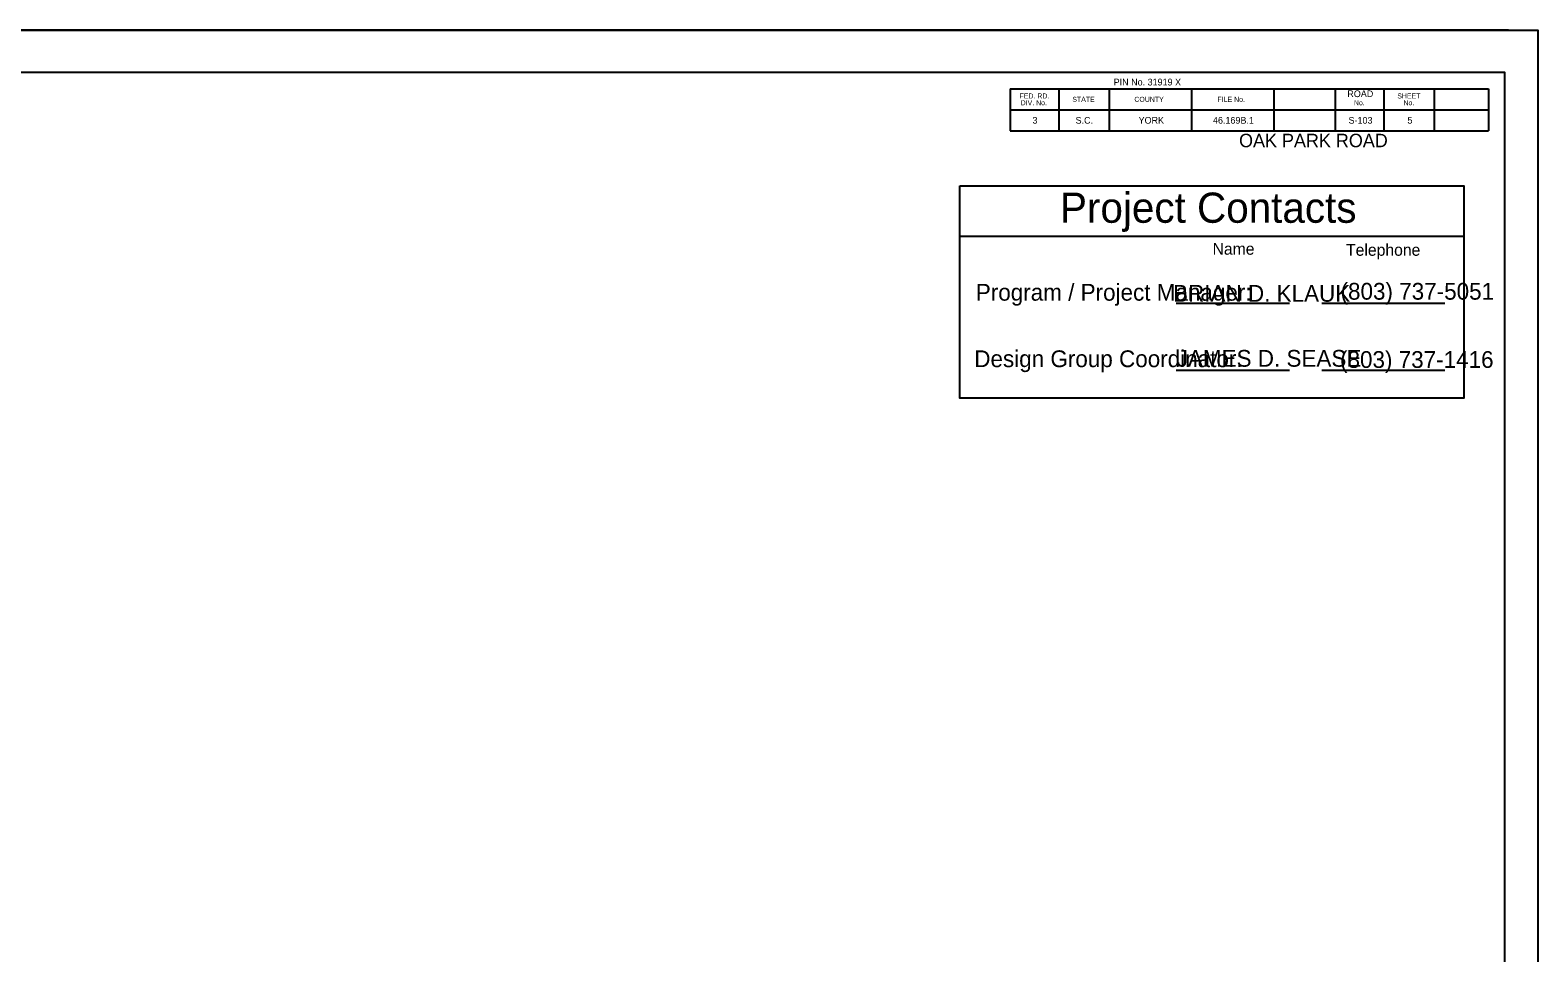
# Model space of a CAD drawing. Extents: x -796 to 2793, y -4650 to 4425.
# Drawn here: x 1879 to 2777, y -2950 to -2400 of the extents above; entities that cross this region are included whole.
import ezdxf

# ---------------------------------------------------------------- set-up
doc = ezdxf.new("R2010")
doc.units = 0
for name, color, linetype in [('RD_HC_CL', 7, 'Continuous'), ('RD_HC_Data', 7, 'Continuous'), ('RD_HC_Data_Tic', 7, 'Continuous'), ('RD_SHT_Bndy', 7, 'Continuous'), ('RD_TX_Misc1', 7, 'Continuous')]:
    doc.layers.add(name, color=color, linetype=linetype)

msp = doc.modelspace()

# ---------------------------------------------------------------- linework, layer by layer
at = {"layer": 'RD_HC_CL'}
msp.add_lwpolyline([(981.4, -2400), (2777.4, -2400), (2777.4, -3500), (981.4, -3500)], close=True, dxfattribs=at)
at = {"layer": 'RD_HC_Data'}
for p, q in [((2760, -2400), (1000, -2400)), ((1000, -2400), (2760, -2400)), ((2463.1, -2435), (2463.1, -2460)), ((2463.1, -2435), (2748.1, -2435)), ((2492.1, -2435), (2492.1, -2460)), ((2522.1, -2435), (2522.1, -2460)), ((2571.1, -2435), (2571.1, -2460)), ((2620.1, -2435), (2620.1, -2460)), ((2656.6, -2435), (2656.6, -2460)), ((2685.6, -2435), (2685.6, -2460)), ((2715.6, -2435), (2715.6, -2460)), ((2748.1, -2435), (2748.1, -2460)), ((2463.1, -2447.5), (2748.1, -2447.5)), ((2463.1, -2460), (2748.1, -2460))]:
    msp.add_line(p, q, dxfattribs=at)
msp.add_lwpolyline([(1082.6, -2425), (2757.6, -2425), (2757.6, -3475), (1082.6, -3475)], close=True, dxfattribs=at)
at = {"layer": 'RD_TX_Misc1'}
for p, q in [((2433.16, -2522.72), (2733.34, -2522.72)), ((2562.03, -2562.72), (2629.41, -2562.72)), ((2648.83, -2562.72), (2721.92, -2562.72)), ((2562.03, -2602.72), (2629.41, -2602.72)), ((2648.83, -2602.72), (2721.92, -2602.72))]:
    msp.add_line(p, q, dxfattribs=at)
msp.add_lwpolyline([(2433.16, -2492.72), (2733.34, -2492.72), (2733.34, -2619.29), (2433.16, -2619.29)], close=True, dxfattribs=at)

# ---------------------------------------------------------------- texts
at = {"layer": 'RD_HC_Data_Tic'}
for s, height, p in [('PIN No. 31919 X   ', 4, (2524.75, -2432.98)), ('FED. RD.', 3, (2468.72, -2440.73)), ('DIV. No.', 3, (2469.34, -2444.77)), ('STATE', 3, (2500.12, -2442.75)), ('COUNTY', 3, (2537.09, -2442.75)), ('FILE No.', 3, (2586.6, -2442.75)), ('      ROAD      ', 4, (2655.02, -2439.93)), ('No.', 3, (2667.86, -2444.77)), ('SHEET', 3, (2693.68, -2440.73)), ('No.', 3, (2697.36, -2444.77)), ('3', 4, (2476.4, -2455.75)), ('S.C.', 4, (2502.08, -2455.75)), ('      YORK      ', 4, (2530.68, -2455.75)), ('   46.169B.1    ', 4, (2579.44, -2455.75)), ('     S-103      ', 4, (2657.22, -2455.75)), ('       5        ', 4, (2689.34, -2455.75)), ('OAK PARK ROAD                 ', 8, (2599.44, -2469.78))]:
    msp.add_text(s, height=height, dxfattribs=at).set_placement(p)
at = {"layer": 'RD_SHT_Bndy'}
for s, p in [('(803) 737-5051', (2659.89, -2560.66)), ('BRIAN D. KLAUK', (2560.14, -2561.89)), ('JAMES D. SEASE', (2562.29, -2600.63)), ('(803) 737-1416', (2659.58, -2601.34))]:
    msp.add_text(s, height=10, dxfattribs=at).set_placement(p)
at = {"layer": 'RD_TX_Misc1'}
for s, height, p in [('Project Contacts', 18, (2492.81, -2514.83)), ('Name', 7, (2583.65, -2533.86)), ('Telephone', 7, (2663.17, -2534.49)), ('Program / Project Manager:', 10, (2442.65, -2561.26)), ('Design Group Coordinator:', 10, (2441.73, -2600.88))]:
    msp.add_text(s, height=height, dxfattribs=at).set_placement(p)

doc.saveas('drawing.dxf')
